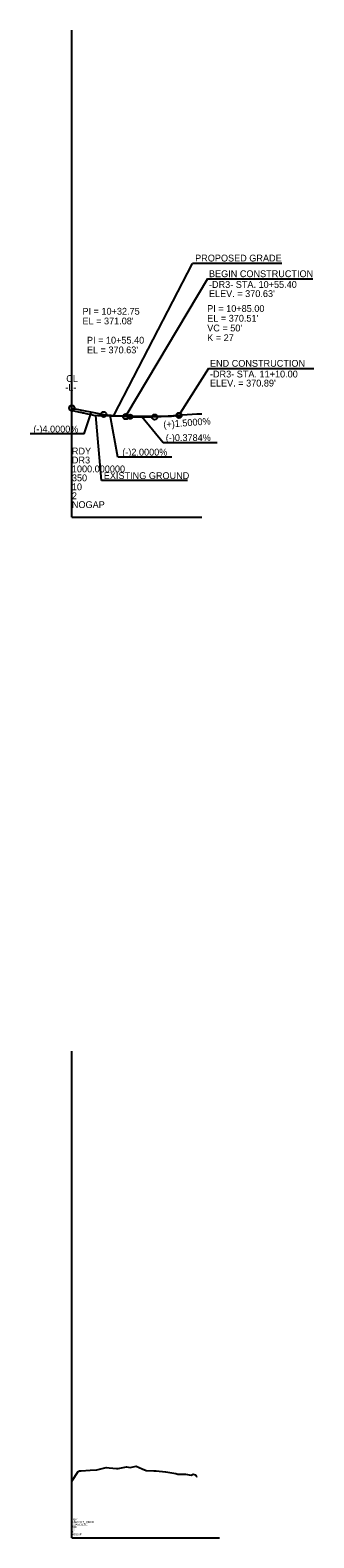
# Model space of a CAD drawing. Extents: x 1625686 to 1640492, y 1161393 to 1175642.
# Drawn here: x 1630174 to 1630466, y 1161451 to 1162999 of the extents above; entities that cross this region are included whole.
import ezdxf

# ---------------------------------------------------------------- set-up
doc = ezdxf.new("R2010")
doc.units = 0
for name, color, linetype in [('Exist Profile Cell', 7, 'Continuous'), ('Exist Vertical Profile Ground Line', 7, 'Continuous'), ('Prop Vertical Profile Curve Label', 7, 'Continuous'), ('Prop Vertical Profile Grade', 7, 'Continuous'), ('Prop Vertical Profile Grade Label', 7, 'Continuous'), ('Prop VPI Label', 7, 'Continuous')]:
    doc.layers.add(name, color=color, linetype=linetype)

msp = doc.modelspace()

# ---------------------------------------------------------------- linework, layer by layer
at = {"layer": 'Exist Profile Cell'}
for p, q in [((1630217, 1162499.2), (1630217, 1162999.2)), ((1630217, 1162499.2), (1630350.7, 1162499.2)), ((1630217, 1162499.2), (1630217, 1162499.2)), ((1630217, 1161450.8), (1630217, 1161950.8)), ((1630217, 1161450.8), (1630368.9, 1161450.8)), ((1630217, 1161450.8), (1630217, 1161450.8))]:
    msp.add_line(p, q, dxfattribs=at)
at = {"layer": 'Exist Vertical Profile Ground Line'}
for points in [[(1630217, 1162608.7), (1630217.3, 1162608.7), (1630225.1, 1162607), (1630226.6, 1162606.7), (1630228.1, 1162606.2), (1630229.4, 1162606.2), (1630231.7, 1162605.6), (1630239.2, 1162603.7), (1630243.7, 1162603.3), (1630247.8, 1162603.3), (1630255.6, 1162603.1), (1630263.8, 1162603.2), (1630264.6, 1162603.2), (1630277.7, 1162603), (1630292.6, 1162602.8), (1630305.4, 1162602.8), (1630319.3, 1162602.9), (1630330.8, 1162604), (1630345.3, 1162605.3), (1630350.7, 1162605.2)], [(1630217, 1161509.1), (1630223.4, 1161519), (1630225, 1161519.6), (1630226.6, 1161519.6), (1630235.8, 1161520.5), (1630242.6, 1161520.8), (1630252.2, 1161523.1), (1630252.7, 1161523.2), (1630255.2, 1161522.7), (1630262.9, 1161522), (1630264.5, 1161522), (1630273, 1161523.7), (1630276.8, 1161523), (1630283.2, 1161524.3), (1630289.1, 1161521.8), (1630293.3, 1161520.1), (1630301.4, 1161519.7), (1630303.5, 1161519.8), (1630313.3, 1161518.6), (1630313.7, 1161518.5), (1630323.8, 1161516.9), (1630326, 1161516.4), (1630333.9, 1161516.2), (1630339.5, 1161515.3), (1630341.6, 1161516.1), (1630344, 1161515.5), (1630345.3, 1161513.7), (1630345.8, 1161513.8)]]:
    msp.add_lwpolyline(points, dxfattribs=at)
at = {"layer": 'Prop Vertical Profile Curve Label'}
for q in [(1630217, 1162626.3), (1630217, 1162607.3)]:
    msp.add_line((1630217, 1162611.1), q, dxfattribs=at)
for centre in [(1630277, 1162602.2), (1630327, 1162603.6)]:
    msp.add_circle(centre, 2.25, dxfattribs=at)
at = {"layer": 'Prop Vertical Profile Grade'}
for p, q in [((1630217, 1162611.1), (1630249.7, 1162604.6)), ((1630249.7, 1162604.6), (1630272.4, 1162602.3)), ((1630272.4, 1162602.3), (1630277, 1162602.2))]:
    msp.add_line(p, q, dxfattribs=at)
msp.add_spline([(1630277, 1162602.2), (1630278, 1162602.2), (1630279, 1162602.2), (1630280, 1162602.2), (1630281, 1162602.2), (1630282, 1162602.2), (1630283, 1162602.2), (1630284, 1162602.1), (1630285, 1162602.1), (1630286, 1162602.1), (1630287, 1162602.1), (1630288, 1162602.1), (1630289, 1162602.1), (1630290, 1162602.1), (1630291, 1162602.1), (1630292, 1162602.2), (1630293, 1162602.2), (1630294, 1162602.2), (1630295, 1162602.2), (1630296, 1162602.2), (1630297, 1162602.2), (1630298, 1162602.2), (1630299, 1162602.3), (1630300, 1162602.3), (1630301, 1162602.3), (1630302, 1162602.3), (1630303, 1162602.4), (1630304, 1162602.4), (1630305, 1162602.4), (1630306, 1162602.5), (1630307, 1162602.5), (1630308, 1162602.5), (1630309, 1162602.6), (1630310, 1162602.6), (1630311, 1162602.7), (1630312, 1162602.7), (1630313, 1162602.8), (1630314, 1162602.8), (1630315, 1162602.9), (1630316, 1162602.9), (1630317, 1162603), (1630318, 1162603), (1630319, 1162603.1), (1630320, 1162603.2), (1630321, 1162603.2), (1630322, 1162603.3), (1630323, 1162603.3), (1630324, 1162603.4), (1630325, 1162603.5), (1630326, 1162603.6), (1630327, 1162603.6)], degree=3, dxfattribs=at)
at = {"layer": 'Prop Vertical Profile Grade Label'}
for p, q in [((1630260, 1162603.6), (1630340.9, 1162759.4)), ((1630432.8, 1162759.4), (1630340.9, 1162759.4)), ((1630356.3, 1162743.8), (1630273.4, 1162604.9)), ((1630356.3, 1162743.8), (1630464.7, 1162743.8)), ((1630357.3, 1162651.8), (1630328.4, 1162606)), ((1630357.3, 1162651.8), (1630465.7, 1162651.8)), ((1630229.7, 1162584.5), (1630237, 1162607.1)), ((1630264.3, 1162560.5), (1630256.2, 1162603.9)), ((1630310.7, 1162575.3), (1630289, 1162602)), ((1630229.7, 1162584.5), (1630174.1, 1162584.5)), ((1630366.3, 1162575.3), (1630310.7, 1162575.3)), ((1630319.9, 1162560.5), (1630264.3, 1162560.5))]:
    msp.add_line(p, q, dxfattribs=at)
at = {"layer": 'Prop VPI Label'}
for p, q in [((1630247.3, 1162536.8), (1630241.5, 1162603.5)), ((1630277, 1162602.2), (1630299.2, 1162601.8)), ((1630327, 1162603.6), (1630304.7, 1162602)), ((1630335.9, 1162536.8), (1630247.3, 1162536.8))]:
    msp.add_line(p, q, dxfattribs=at)
for centre in [(1630217, 1162611.1), (1630249.7, 1162604.6), (1630272.4, 1162602.3), (1630302, 1162601.8), (1630327, 1162603.6)]:
    msp.add_circle(centre, 2.75, dxfattribs=at)

# ---------------------------------------------------------------- texts
at = {"layer": 'Exist Profile Cell'}
for s, height, p in [('RDY', 7, (1630217, 1162563.4)), ('DR3', 7, (1630217, 1162554.2)), ('1000.000000', 7, (1630217, 1162545.1)), ('350', 7, (1630217, 1162535.9)), ('10', 7, (1630217, 1162526.7)), ('2', 7, (1630217, 1162517.5)), ('NOGAP', 7, (1630217, 1162508.4)), ('RDY', 2, (1630217, 1161468.6)), ('PARCEL7_18RCP', 2, (1630217, 1161466)), ('1000.000000', 2, (1630217, 1161463.5)), ('350', 2, (1630217, 1161461)), ('2', 2, (1630217, 1161455.9)), ('10', 2, (1630217, 1161458.4)), ('NOGAP', 2, (1630217, 1161453.4))]:
    msp.add_text(s, height=height, dxfattribs=at).set_placement(p)
at = {"layer": 'Prop Vertical Profile Grade Label'}
for s, p in [('PROPOSED GRADE', (1630343.7, 1162761.6)), ('(-)4.0000%', (1630177.4, 1162586)), ('(-)2.0000%', (1630268.8, 1162562.3))]:
    msp.add_text(s, height=7, dxfattribs=at).set_placement(p)
for s, rotation, p in [('(+)1.5000%', 4.2892, (1630311.3, 1162590.7)), ('(-)0.3784%', 360, (1630313.5, 1162577.2))]:
    msp.add_text(s, height=7, rotation=rotation, dxfattribs=at).set_placement(p)
at = {"layer": 'Prop VPI Label'}
for s, p in [('BEGIN CONSTRUCTION', (1630357.9, 1162745.5)), ('-DR3- STA. 10+55.40', (1630357.9, 1162734.5)), ("ELEV. = 370.63'", (1630357.9, 1162725.1)), ('PI = 10+32.75', (1630227.9, 1162707)), ("EL = 371.08'", (1630227.9, 1162697)), ('PI = 10+85.00', (1630356.1, 1162709.8)), ("EL = 370.51'", (1630356.1, 1162699.8)), ("VC = 50'", (1630356.1, 1162689.8)), ('PI = 10+55.40', (1630232.5, 1162677.3)), ("EL = 370.63'", (1630232.5, 1162667.3)), ('K = 27', (1630356.1, 1162679.8)), ('END CONSTRUCTION', (1630358.9, 1162653.5)), ('CL', (1630211.2, 1162637.9)), ('-DR3- STA. 11+10.00', (1630358.9, 1162642.5)), ('-L-', (1630210.2, 1162628.8)), ("ELEV. = 370.89'", (1630358.9, 1162633.2)), ('EXISTING GROUND', (1630249.8, 1162538.2))]:
    msp.add_text(s, height=7, dxfattribs=at).set_placement(p)

doc.saveas('drawing.dxf')
